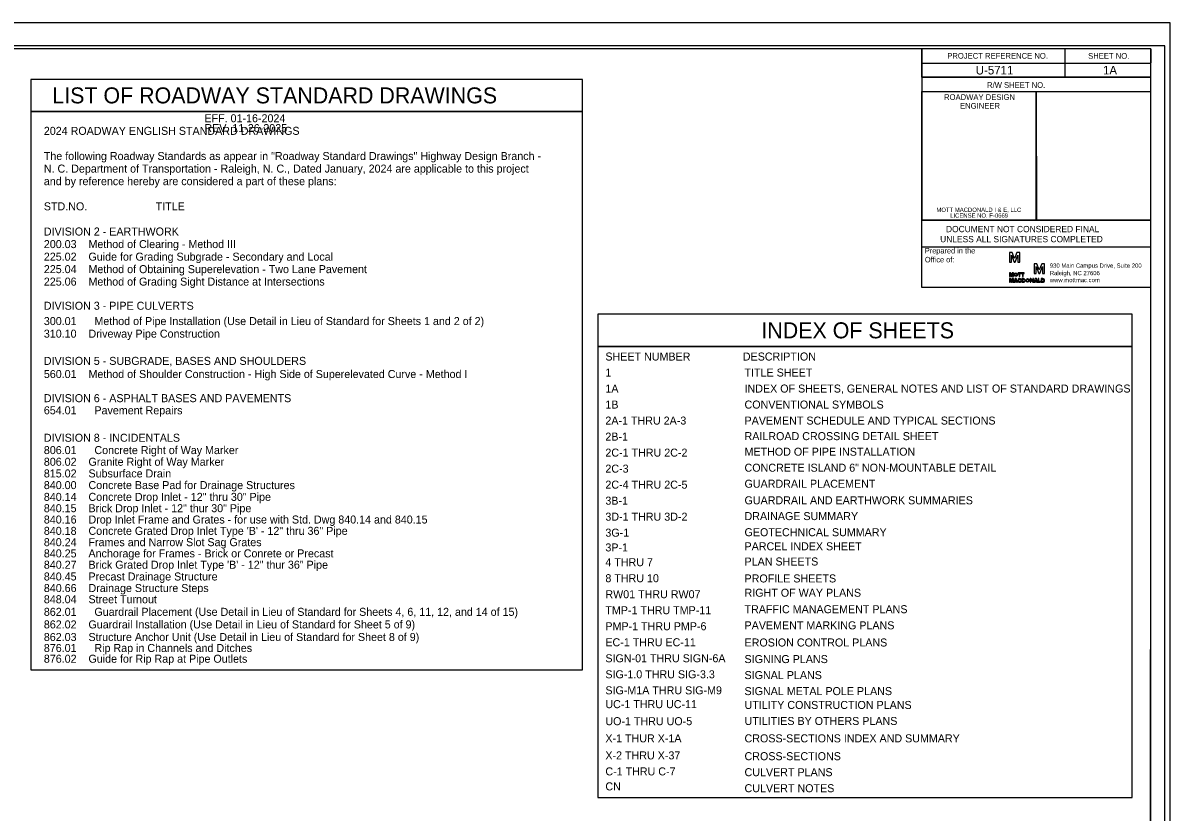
# Model space of a CAD drawing. Extents: x 1756641 to 5864777, y 736593 to 1246112.
# Drawn here: x 5863774 to 5864777, y 1245422 to 1246112 of the extents above; entities that cross this region are included whole.
import ezdxf

# ---------------------------------------------------------------- set-up
doc = ezdxf.new("R2010")
doc.units = 0
for name, color, linetype in [('Default', 7, 'Continuous'), ('Old_Level_14', 7, 'Continuous'), ('Old_Level_2', 7, 'Continuous'), ('Old_Level_42', 7, 'Continuous'), ('Old_Level_45', 7, 'Continuous'), ('Scratch_Level_1', 7, 'Continuous'), ('Scratch_Level_3', 7, 'Continuous'), ('Sheet Cutting Line CELL', 7, 'Continuous'), ('Sheet Plan CELL', 7, 'Continuous'), ('Sheet Plot Border Inside CELL', 7, 'Continuous'), ('Sheet Plot Border Outside CELL', 7, 'Continuous'), ('Sheet Sticker Exception Certification CELL', 7, 'Continuous')]:
    doc.layers.add(name, color=color, linetype=linetype)

msp = doc.modelspace()

# ---------------------------------------------------------------- linework, layer by layer
at = {"layer": 'Old_Level_14'}
for points in [[(5863780.4, 1245546.1), (5864262.9, 1245546.1), (5864262.9, 1246034.2), (5863780.4, 1246034.2)], [(5864276.4, 1245434.4), (5864743.6, 1245434.4), (5864743.6, 1245828.8), (5864276.4, 1245828.8)]]:
    msp.add_lwpolyline(points, close=True, dxfattribs=at)
at = {"layer": 'Old_Level_2'}
for p, q in [((5864638.8, 1245910.9), (5864636.3, 1245910.9)), ((5864636.3, 1245910.9), (5864636.3, 1245902.4)), ((5864638.1, 1245902.4), (5864638.1, 1245908.5)), ((5864638.1, 1245908.5), (5864638.1, 1245908.5)), ((5864638.1, 1245908.5), (5864640.5, 1245902.4)), ((5864640.8, 1245905.6), (5864638.8, 1245910.9)), ((5864640.9, 1245905.6), (5864640.8, 1245905.6)), ((5864640.8, 1245905.6), (5864640.8, 1245905.6)), ((5864642.9, 1245910.9), (5864640.9, 1245905.6)), ((5864640.9, 1245905.6), (5864640.9, 1245905.6)), ((5864641.3, 1245902.4), (5864643.7, 1245908.5)), ((5864645.5, 1245910.9), (5864642.9, 1245910.9)), ((5864643.7, 1245908.5), (5864643.7, 1245908.5)), ((5864643.7, 1245908.5), (5864643.7, 1245902.4)), ((5864645.5, 1245902.4), (5864645.5, 1245910.9)), ((5864636.3, 1245902.4), (5864638.1, 1245902.4)), ((5864637.2, 1245893.1), (5864636.3, 1245893.1)), ((5864636.3, 1245893.1), (5864636.3, 1245889.8)), ((5864638, 1245891.1), (5864637.2, 1245893.1)), ((5864638.8, 1245893.1), (5864638, 1245891.1)), ((5864639.8, 1245893.1), (5864638.8, 1245893.1)), ((5864639.8, 1245889.8), (5864639.8, 1245893.1)), ((5864639.8, 1245889.8), (5864639.8, 1245893.1)), ((5864640.5, 1245902.4), (5864641.3, 1245902.4)), ((5864643.7, 1245902.4), (5864645.5, 1245902.4)), ((5864660.4, 1245901), (5864657.9, 1245901)), ((5864657.9, 1245901), (5864657.9, 1245892.5)), ((5864657.9, 1245892.5), (5864659.7, 1245892.5)), ((5864659.7, 1245892.5), (5864659.7, 1245898.6)), ((5864659.7, 1245898.6), (5864659.7, 1245898.6)), ((5864659.7, 1245898.6), (5864662.1, 1245892.5)), ((5864662.5, 1245895.7), (5864660.4, 1245901)), ((5864662.1, 1245892.5), (5864662.9, 1245892.5)), ((5864664.6, 1245901), (5864662.5, 1245895.7)), ((5864662.5, 1245895.7), (5864662.5, 1245895.7)), ((5864662.5, 1245895.7), (5864662.5, 1245895.7)), ((5864662.5, 1245895.7), (5864662.5, 1245895.7)), ((5864662.9, 1245892.5), (5864665.3, 1245898.6)), ((5864667.1, 1245901), (5864664.6, 1245901)), ((5864665.3, 1245898.6), (5864665.3, 1245898.6)), ((5864665.3, 1245898.6), (5864665.3, 1245892.5)), ((5864665.3, 1245892.5), (5864667.1, 1245892.5)), ((5864667.1, 1245892.5), (5864667.1, 1245901)), ((5864636.3, 1245889.8), (5864636.9, 1245889.8)), ((5864637.2, 1245888), (5864636.3, 1245888)), ((5864636.3, 1245888), (5864636.3, 1245884.8)), ((5864636.3, 1245884.8), (5864636.9, 1245884.8)), ((5864636.9, 1245889.8), (5864636.9, 1245892.2)), ((5864636.9, 1245892.2), (5864637, 1245892.2)), ((5864636.9, 1245892.2), (5864637, 1245892.2)), ((5864636.9, 1245884.8), (5864636.9, 1245887.1)), ((5864636.9, 1245887.1), (5864637, 1245887.1)), ((5864637, 1245892.2), (5864637.9, 1245889.8)), ((5864637, 1245887.1), (5864637.9, 1245884.8)), ((5864638, 1245886), (5864637.2, 1245888)), ((5864637.9, 1245889.8), (5864638.2, 1245889.8)), ((5864637.9, 1245884.8), (5864638.2, 1245884.8)), ((5864638.8, 1245888), (5864638, 1245886)), ((5864638.2, 1245889.8), (5864639.1, 1245892.2)), ((5864638.2, 1245884.8), (5864639.1, 1245887.1)), ((5864639.8, 1245888), (5864638.8, 1245888)), ((5864639.1, 1245892.2), (5864639.1, 1245892.2)), ((5864639.1, 1245892.2), (5864639.1, 1245889.8)), ((5864639.1, 1245892.2), (5864639.1, 1245892.2)), ((5864639.1, 1245892.2), (5864639.1, 1245892.2)), ((5864639.1, 1245889.8), (5864639.8, 1245889.8)), ((5864639.1, 1245887.1), (5864639.1, 1245887.1)), ((5864639.1, 1245887.1), (5864639.1, 1245884.8)), ((5864639.1, 1245884.8), (5864639.8, 1245884.8)), ((5864639.8, 1245884.8), (5864639.8, 1245888)), ((5864646.1, 1245887), (5864646.7, 1245887.2)), ((5864646.1, 1245887), (5864646.7, 1245887.2)), ((5864646.6, 1245885.5), (5864646.1, 1245885.7)), ((5864646.6, 1245885.5), (5864646.1, 1245885.7)), ((5864648.6, 1245888), (5864647.2, 1245888)), ((5864647.2, 1245888), (5864647.2, 1245886.4)), ((5864647.2, 1245886.4), (5864647.2, 1245884.8)), ((5864647.2, 1245884.8), (5864648.6, 1245884.8)), ((5864647.8, 1245885.4), (5864647.8, 1245887.4)), ((5864647.8, 1245887.4), (5864648.6, 1245887.4)), ((5864648.6, 1245885.4), (5864647.8, 1245885.4)), ((5864664, 1245888), (5864664, 1245888)), ((5864665.5, 1245888), (5864664, 1245888)), ((5864664, 1245888), (5864664, 1245886.4)), ((5864664, 1245886.4), (5864664, 1245884.8)), ((5864664, 1245884.8), (5864665.5, 1245884.8)), ((5864664.7, 1245885.4), (5864664.7, 1245887.4)), ((5864664.7, 1245887.4), (5864665.5, 1245887.4)), ((5864665.5, 1245885.4), (5864664.7, 1245885.4)), ((5864665.5, 1245887.4), (5864665.5, 1245887.4))]:
    msp.add_line(p, q, dxfattribs=at)
for points in [[(5864643.9, 1245892.5), (5864644.8, 1245892.5), (5864644.8, 1245889.8), (5864645.5, 1245889.8), (5864645.5, 1245892.5), (5864646.5, 1245892.5), (5864646.5, 1245893.1), (5864643.9, 1245893.1), (5864643.9, 1245892.5)], [(5864646.9, 1245892.5), (5864647.8, 1245892.5), (5864647.8, 1245889.8), (5864648.5, 1245889.8), (5864648.5, 1245892.5), (5864649.4, 1245892.5), (5864649.4, 1245893.1), (5864646.9, 1245893.1), (5864646.9, 1245892.5)], [(5864640.2, 1245884.8), (5864641, 1245884.8), (5864641.2, 1245885.3), (5864642.6, 1245885.3), (5864642.8, 1245884.8), (5864643.5, 1245884.8), (5864642.3, 1245888), (5864641.4, 1245888), (5864640.2, 1245884.8)], [(5864641.4, 1245885.9), (5864641.9, 1245887.3), (5864642.4, 1245885.9), (5864641.4, 1245885.9)], [(5864655.1, 1245886.9), (5864655.1, 1245886.9), (5864656.7, 1245884.8), (5864657.3, 1245884.8), (5864657.3, 1245888), (5864656.7, 1245888), (5864656.7, 1245886), (5864655.1, 1245888), (5864654.5, 1245888), (5864654.5, 1245884.8), (5864655.1, 1245884.8), (5864655.1, 1245886.9)], [(5864657.8, 1245884.8), (5864658.5, 1245884.8), (5864658.8, 1245885.3), (5864660.2, 1245885.3), (5864660.4, 1245884.8), (5864661.1, 1245884.8), (5864659.9, 1245888), (5864659, 1245888), (5864657.8, 1245884.8)], [(5864658.9, 1245885.9), (5864659.5, 1245887.3), (5864660, 1245885.9), (5864658.9, 1245885.9)], [(5864663.6, 1245884.8), (5864663.6, 1245885.4), (5864662.2, 1245885.4), (5864662.2, 1245888), (5864661.5, 1245888), (5864661.5, 1245884.8), (5864663.6, 1245884.8)], [(5864663.6, 1245884.8), (5864663.6, 1245885.4), (5864662.2, 1245885.4), (5864662.2, 1245888), (5864661.5, 1245888), (5864661.5, 1245884.8), (5864663.6, 1245884.8), (5864663.6, 1245885.4)]]:
    msp.add_lwpolyline(points, dxfattribs=at)
msp.add_arc((5864665.5, 1245886.4), 1.62, 270, 90, dxfattribs=at)
for centre, major_axis, ratio in [((5864642, 1245891.5), (0, 1.62), 0.993118), ((5864642, 1245891.5), (0, 1.06), 0.916103), ((5864652.3, 1245886.4), (0, 1.62), 0.993118), ((5864652.3, 1245886.4), (0, 1.06), 0.916103)]:
    msp.add_ellipse(centre, major_axis=major_axis, ratio=ratio, dxfattribs=at)
for centre, major_axis, ratio, start_param, end_param in [((5864645.3, 1245886.4), (0, 1.62), 0.993118, 5.246647, 10.366427), ((5864645.3, 1245886.4), (0, 1.62), 0.993118, 5.246647, 10.366427), ((5864645.3, 1245886.4), (0, 1.06), 0.916103, 5.276876, 9.424778), ((5864645.3, 1245886.4), (0, 1.06), 0.916103, 5.276876, 10.296021), ((5864645.3, 1245886.4), (0, 1.06), 0.916103, 3.141593, 4.012835), ((5864648.6, 1245886.4), (0, -1.62), 0.930276, 0, 3.141593), ((5864648.6, 1245886.4), (0, -1.01), 0.900832, 0, 3.141593), ((5864665.5, 1245886.4), (0, -1.01), 0.900832, 0, 3.141593)]:
    msp.add_ellipse(centre, major_axis=major_axis, ratio=ratio, start_param=start_param, end_param=end_param, dxfattribs=at)
at = {"layer": 'Old_Level_42'}
msp.add_lwpolyline([(5864759.9, 1245880.2), (5864559.8, 1245880.2), (5864559.8, 1245915.5)], dxfattribs=at)
at = {"layer": 'Scratch_Level_1'}
for points in [[(5863780.4, 1246034.2), (5864262.9, 1246034.2), (5864262.9, 1246062.2), (5863780.4, 1246062.2)], [(5864276.4, 1245828.8), (5864743.6, 1245828.8), (5864743.6, 1245856.8), (5864276.4, 1245856.8)]]:
    msp.add_lwpolyline(points, close=True, dxfattribs=at)
at = {"layer": 'Sheet Cutting Line CELL'}
msp.add_line((5864776.8, 1246111.5), (5863093.3, 1246111.5), dxfattribs=at)
at = {"layer": 'Sheet Plan CELL'}
for p, q in [((5864684.8, 1246089), (5864684.9, 1246064)), ((5864559.8, 1246076.5), (5864759.8, 1246076.5)), ((5864559.8, 1246064), (5864759.8, 1246064)), ((5864659.8, 1246051.5), (5864659.9, 1245939)), ((5864759.8, 1245890.4), (5864759.8, 1245877.9))]:
    msp.add_line(p, q, dxfattribs=at)
for points in [[(5863259.8, 1245039), (5863259.8, 1246089), (5864559.8, 1246089.1), (5864559.8, 1245939), (5864759.8, 1245939), (5864759.8, 1245039)], [(5864759.9, 1246089), (5863259.8, 1246089), (5863259.8, 1245039), (5864759.8, 1245039)], [(5864559.8, 1246089.1), (5864759.9, 1246089), (5864759.8, 1246064), (5864559.8, 1246064)], [(5864559.8, 1246051.5), (5864659.8, 1246051.5), (5864659.8, 1245939), (5864559.8, 1245939)], [(5864659.8, 1246051.5), (5864759.8, 1246051.5), (5864759.8, 1245939), (5864659.8, 1245939)]]:
    msp.add_lwpolyline(points, close=True, dxfattribs=at)
at = {"layer": 'Sheet Plot Border Inside CELL'}
msp.add_lwpolyline([(5863106.3, 1245036.5), (5864772.3, 1245036.5), (5864772.3, 1246091.5), (5863106.3, 1246091.5)], close=True, dxfattribs=at)
at = {"layer": 'Sheet Plot Border Outside CELL'}
msp.add_lwpolyline([(5863093.3, 1245016.5), (5864776.8, 1245016.5), (5864776.8, 1246111.5), (5863093.3, 1246111.5)], close=True, dxfattribs=at)
at = {"layer": 'Sheet Sticker Exception Certification CELL'}
for p, q in [((5864559.8, 1245915.5), (5864559.8, 1245939)), ((5864559.8, 1245939), (5864759.8, 1245939)), ((5864759.8, 1245939), (5864759.8, 1245915.5)), ((5864759.8, 1245915.5), (5864559.8, 1245915.5))]:
    msp.add_line(p, q, dxfattribs=at)

# ---------------------------------------------------------------- texts
at = {"layer": 'Default'}
for s, p in [('840.00    Concrete Base Pad for Drainage Structures', (5863791.9, 1245704)), ('840.14    Concrete Drop Inlet - 12" thru 30" Pipe', (5863791.9, 1245693.7)), ('840.15    Brick Drop Inlet - 12" thur 30" Pipe', (5863791.9, 1245683.8)), ('840.16    Drop Inlet Frame and Grates - for use with Std. Dwg 840.14 and 840.15', (5863791.9, 1245673.9)), ('840.18    Concrete Grated Drop Inlet Type \'B\' - 12" thru 36" Pipe', (5863791.9, 1245664)), ('840.24    Frames and Narrow Slot Sag Grates', (5863791.9, 1245654.1)), ('840.25    Anchorage for Frames - Brick or Conrete or Precast', (5863791.9, 1245644.3)), ('840.27    Brick Grated Drop Inlet Type \'B\' - 12" thur 36" Pipe', (5863791.9, 1245634.4))]:
    msp.add_text(s, height=7, dxfattribs=at).set_placement(p)
at = {"layer": 'Old_Level_14'}
for s, p in [('                                                      EFF. 01-16-2024', (5863791.9, 1246024.7)), ('                                                      REV. 11-26-2025', (5863791.9, 1246016.1)), ('2024 ROADWAY ENGLISH STANDARD DRAWINGS', (5863791.9, 1246013.7)), ('The following Roadway Standards as appear in "Roadway Standard Drawings" Highway Design Branch -', (5863791.9, 1245991.7)), ('N. C. Department of Transportation - Raleigh, N. C., Dated January, 2024 are applicable to this project', (5863791.9, 1245980.7)), ('and by reference hereby are considered a part of these plans:', (5863791.9, 1245969.7)), ('STD.NO.                       TITLE', (5863791.9, 1245947.7)), ('DIVISION 2 - EARTHWORK', (5863791.9, 1245925.7)), ('200.03    Method of Clearing - Method III', (5863791.9, 1245914.7)), ('225.02    Guide for Grading Subgrade - Secondary and Local', (5863791.9, 1245903.7)), ('225.04    Method of Obtaining Superelevation - Two Lane Pavement', (5863791.9, 1245892.8)), ('225.06    Method of Grading Sight Distance at Intersections', (5863791.9, 1245881.9)), ('DIVISION 3 - PIPE CULVERTS', (5863791.9, 1245860.8)), ('300.01      Method of Pipe Installation (Use Detail in Lieu of Standard for Sheets 1 and 2 of 2)', (5863791.9, 1245847.4)), ('310.10    Driveway Pipe Construction ', (5863791.9, 1245836.4)), ('SHEET NUMBER', (5864283, 1245816.4)), ('DESCRIPTION', (5864403.2, 1245816.4)), ('DIVISION 5 - SUBGRADE, BASES AND SHOULDERS', (5863791.9, 1245812.6)), ('560.01    Method of Shoulder Construction - High Side of Superelevated Curve - Method I', (5863791.9, 1245801.1)), ('1 ', (5864283, 1245802.4)), ('TITLE SHEET', (5864404.7, 1245802.4)), ('1A ', (5864283, 1245788.4)), ('INDEX OF SHEETS, GENERAL NOTES AND LIST OF STANDARD DRAWINGS', (5864404.7, 1245788.4)), ('DIVISION 6 - ASPHALT BASES AND PAVEMENTS', (5863791.9, 1245780)), ('654.01      Pavement Repairs', (5863791.9, 1245769.4)), ('1B  ', (5864283, 1245774.4)), ('CONVENTIONAL SYMBOLS ', (5864404.7, 1245774.4)), ('2A-1 THRU 2A-3', (5864283, 1245760.4)), ('PAVEMENT SCHEDULE AND TYPICAL SECTIONS', (5864404.7, 1245760.4)), ('DIVISION 8 - INCIDENTALS', (5863791.9, 1245745.4)), ('2B-1', (5864283, 1245746.4)), ('RAILROAD CROSSING DETAIL SHEET', (5864404.7, 1245746.8)), ('806.01      Concrete Right of Way Marker', (5863791.9, 1245734.6)), ('2C-1 THRU 2C-2   ', (5864283, 1245732.4)), ('METHOD OF PIPE INSTALLATION', (5864404.7, 1245733.2)), ('806.02    Granite Right of Way Marker', (5863791.9, 1245724.4)), ('2C-3   ', (5864283, 1245718.4)), ('CONCRETE ISLAND 6" NON-MOUNTABLE DETAIL', (5864404.7, 1245719.2)), ('815.02    Subsurface Drain', (5863791.9, 1245714.2)), ('GUARDRAIL PLACEMENT', (5864404.7, 1245705.2)), ('2C-4 THRU 2C-5 ', (5864283, 1245704.4)), ('3B-1 ', (5864283, 1245690.4)), ('GUARDRAIL AND EARTHWORK SUMMARIES', (5864404.7, 1245690.7)), ('3D-1 THRU 3D-2', (5864283, 1245676.4)), ('DRAINAGE SUMMARY', (5864404.7, 1245676.9)), ('3G-1', (5864283, 1245662.4)), ('GEOTECHNICAL SUMMARY', (5864404.7, 1245662.8)), ('3P-1     ', (5864283, 1245649.5)), ('PARCEL INDEX SHEET', (5864404.7, 1245650.5)), ('4 THRU 7    ', (5864283, 1245636.6)), ('PLAN SHEETS', (5864404.7, 1245637.2)), ('840.45    Precast Drainage Structure', (5863791.9, 1245624.1)), ('8 THRU 10', (5864283, 1245622.6)), ('PROFILE SHEETS', (5864404.7, 1245622.4)), ('840.66    Drainage Structure Steps', (5863791.9, 1245614)), ('RW01 THRU RW07', (5864283, 1245608.6)), ('RIGHT OF WAY PLANS', (5864404.7, 1245609.9)), ('848.04    Street Turnout', (5863791.9, 1245604.2)), ('TMP-1 THRU TMP-11    ', (5864283, 1245594.6)), ('TRAFFIC MANAGEMENT PLANS', (5864404.7, 1245595.5)), ('862.01      Guardrail Placement (Use Detail in Lieu of Standard for Sheets 4, 6, 11, 12, and 14 of 15)', (5863791.9, 1245593.2)), ('862.02    Guardrail Installation (Use Detail in Lieu of Standard for Sheet 5 of 9)', (5863791.9, 1245582.2)), ('PMP-1 THRU PMP-6   ', (5864283, 1245580.6)), ('PAVEMENT MARKING PLANS', (5864404.7, 1245581.4)), ('862.03    Structure Anchor Unit (Use Detail in Lieu of Standard for Sheet 8 of 9)', (5863791.9, 1245571.2)), ('EC-1 THRU EC-11     ', (5864283, 1245566.6)), ('EROSION CONTROL PLANS', (5864404.7, 1245566.4)), ('876.01      Rip Rap in Channels and Ditches', (5863791.9, 1245561.6)), ('876.02    Guide for Rip Rap at Pipe Outlets', (5863791.9, 1245552.2)), ('SIGN-01 THRU SIGN-6A    ', (5864283, 1245552.6)), ('SIGNING PLANS', (5864404.7, 1245551.9)), ('SIG-1.0 THRU SIG-3.3     ', (5864283, 1245538.6)), ('SIGNAL PLANS', (5864404.7, 1245537.9)), ('SIG-M1A THRU SIG-M9     ', (5864283, 1245524.6)), ('SIGNAL METAL POLE PLANS', (5864404.7, 1245523.9)), ('UC-1 THRU UC-11     ', (5864283, 1245512.5)), ('UTILITY CONSTRUCTION PLANS', (5864404.7, 1245511.8)), ('UO-1 THRU UO-5', (5864283, 1245497.6)), ('UTILITIES BY OTHERS PLANS', (5864404.7, 1245497.8)), ('X-1 THUR X-1A ', (5864283, 1245482.6)), ('CROSS-SECTIONS INDEX AND SUMMARY', (5864404.7, 1245482.6)), ('X-2 THRU X-37', (5864283, 1245467.7)), ('CROSS-SECTIONS', (5864404.7, 1245467)), ('C-1 THRU C-7', (5864283, 1245453.7)), ('CULVERT PLANS', (5864404.7, 1245453)), ('CN', (5864283, 1245440.6)), ('CULVERT NOTES', (5864404.7, 1245439))]:
    msp.add_text(s, height=7, dxfattribs=at).set_placement(p)
at = {"layer": 'Old_Level_2'}
for s, height, p in [('Prepared in the ', 4.819, (5864562.4, 1245910)), ('Office of:', 4.82, (5864562.4, 1245902.2)), ('930 Main Campus Drive, Suite 200', 3.75, (5864671.7, 1245897.5)), ('Raleigh, NC 27606', 3.75, (5864671.7, 1245891)), ('www.mottmac.com', 3.75, (5864671.7, 1245884.9))]:
    msp.add_text(s, height=height, rotation=360, dxfattribs=at).set_placement(p)
at = {"layer": 'Old_Level_45'}
for s, p in [('MOTT MACDONALD I & E, LLC', (5864572.5, 1245946.3)), (' LICENSE NO. F-0669', (5864583.1, 1245941.3))]:
    msp.add_text(s, height=3.75, rotation=360, dxfattribs=at).set_placement(p)
at = {"layer": 'Scratch_Level_1'}
for s, p in [('LIST OF ROADWAY STANDARD DRAWINGS', (5863799.3, 1246041.2)), ('INDEX OF SHEETS', (5864419.4, 1245835.8))]:
    msp.add_text(s, height=14, dxfattribs=at).set_placement(p)
at = {"layer": 'Scratch_Level_3'}
for s, p in [('U-5711', (5864606.9, 1246066.5)), ('1A', (5864718.2, 1246066.5))]:
    msp.add_text(s, height=7.5, rotation=0, dxfattribs=at).set_placement(p)
at = {"layer": 'Sheet Plan CELL'}
for s, p in [('PROJECT REFERENCE NO.', (5864582, 1246080.3)), ('SHEET NO.', (5864705.2, 1246080.2)), ('R/W SHEET NO.', (5864616.8, 1246054.8)), ('ROADWAY DESIGN', (5864579.2, 1246044.2)), ('ENGINEER', (5864593.2, 1246036.6))]:
    msp.add_text(s, height=5, rotation=0, dxfattribs=at).set_placement(p)
at = {"layer": 'Sheet Sticker Exception Certification CELL'}
for s, p in [('DOCUMENT NOT CONSIDERED FINAL', (5864580.9, 1245928.6)), ('UNLESS ALL SIGNATURES COMPLETED', (5864575.8, 1245919.8))]:
    msp.add_text(s, height=5.5, dxfattribs=at).set_placement(p)

doc.saveas('drawing.dxf')
